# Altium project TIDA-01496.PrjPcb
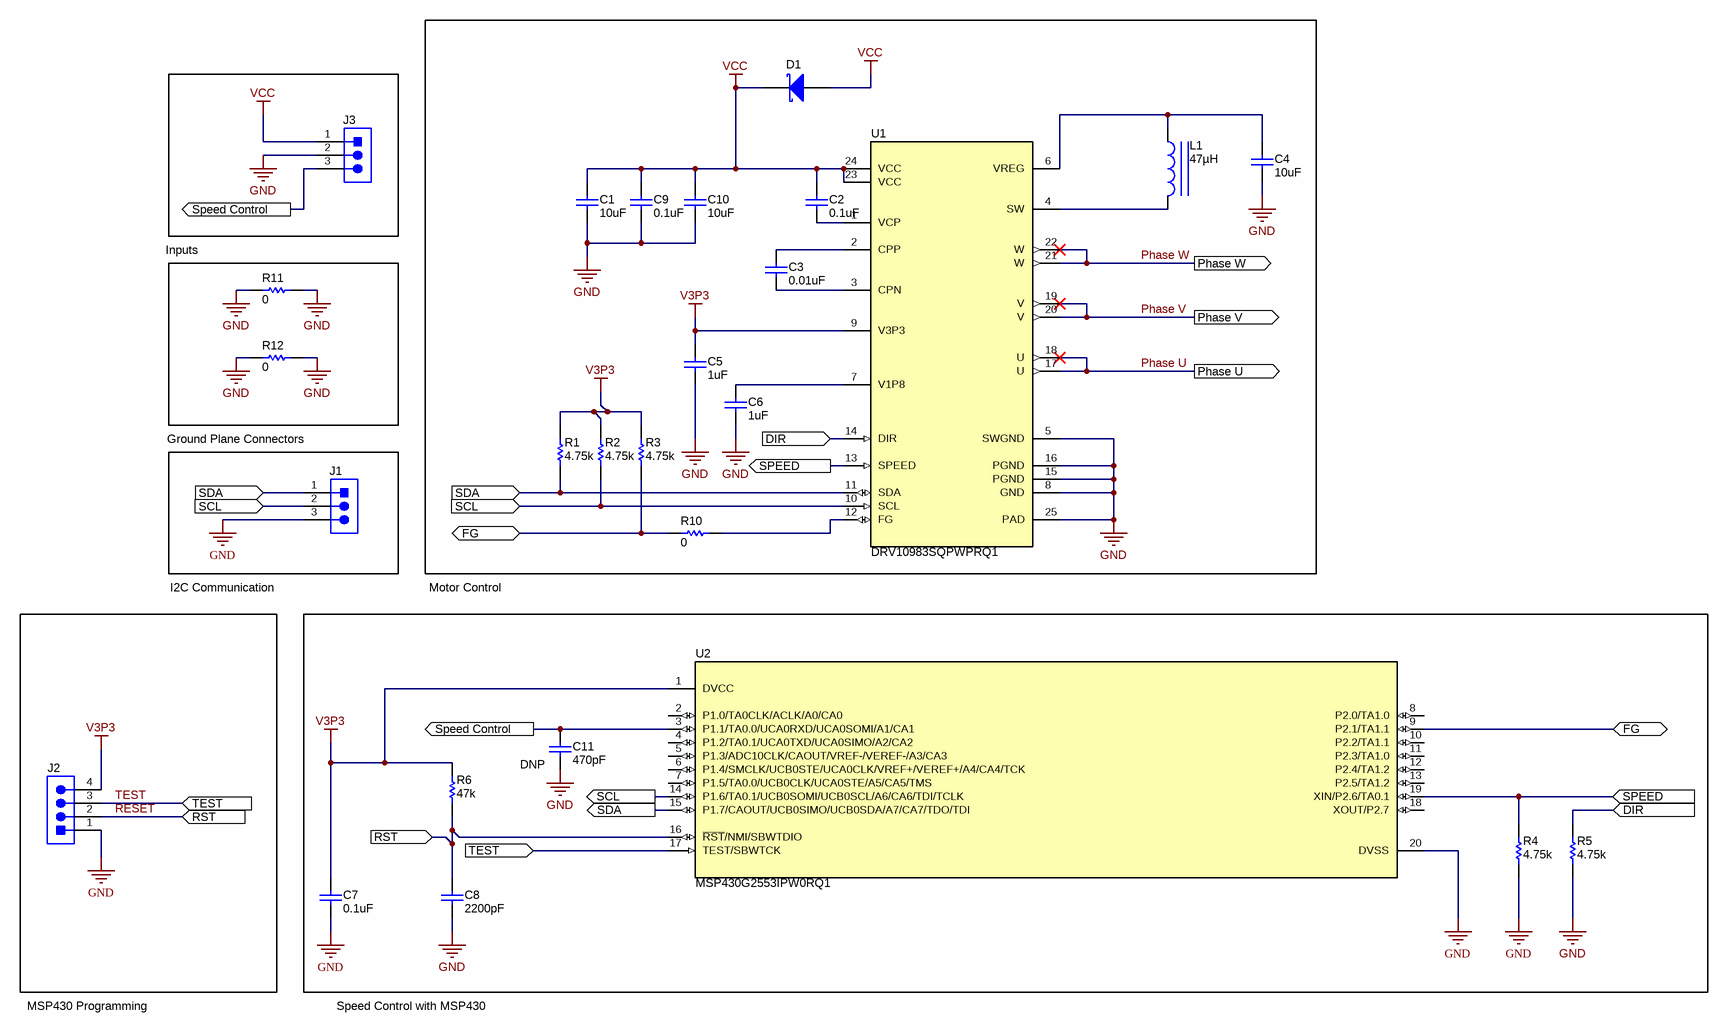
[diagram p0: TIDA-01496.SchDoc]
TID: TIDA-01496; TechSupport: http://www.ti.com/support; SCH_Rev: E2; PRJ_Title: Single-Layer, 12V, Programmable 3-Phase BLDC Motor Driver with Speed Regulation; PRJ_Number: TIDA-01496; PRJ_Engineer: Mostafa Subbar; PRJ_Customer: Public Release; PCB_Rev: E2; PCB_Layout: Mostafa Shubbar; CopyrightYear: 2018
2 sheets, 30 parts. Net scope: flat (ports and power ports of the same name join across sheets).
Board file: TIDA-01496_PCB.PcbDoc
Sheets:
  TIDA-01496.SchDoc
  TIDA-01496_Hardware.SchDoc

## Sheet TIDA-01496.SchDoc
size 431 x 279 mm; Date: Not shown in title block; ApprovedBy: Not shown in title block; CheckedBy: Not shown in title block; Author: Not shown in title block; CompanyName: Not shown in title block; Engineer: Not shown in title block; Organization: Not shown in title block; Address1: Not shown in title block; Address2: Not shown in title block; Address3: Not shown in title block; Address4: Not shown in title block; DocumentNumber: 1; Revision: Use project parameter SCH_Rev; SheetNumber: 1; SheetTotal: 2; PageSetup: Record=PageOptions¦CenterHorizontal=True¦CenterVertical=True¦PrintScale=1.00¦XCorrection=1.00¦YCorrection=1.00¦PrintKind=0¦BorderSize=5000000¦LeftOffset=0¦BottomOffset=0¦Orientation=2¦PaperLength=1000¦PaperWidth=1000¦Scale=100¦PaperSource=15¦PrintQuality=600¦MediaType=1¦DitherType=10¦PrintScaleMode=1¦PaperKind=Letter

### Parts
C1  ValueDisplayed: 10uF  [1206]  (hidden comment: Capacitor)
C2  ValueDisplayed: 0.1uF  [1206_180]  (hidden comment: Capacitor)
C3  ValueDisplayed: 0.01uF  [0603]  (hidden comment: Capacitor)
C4  ValueDisplayed: 10uF  [0603]  (hidden comment: Capacitor)
C5  ValueDisplayed: 1uF  [0603]  (hidden comment: Capacitor)
C6  ValueDisplayed: 1uF  [0603]  (hidden comment: Capacitor)
C7  ValueDisplayed: 0.1uF  [1206]  (hidden comment: Capacitor)
C8  ValueDisplayed: 2200pF  [0805_HV]  (hidden comment: Capacitor)
C9  ValueDisplayed: 0.1uF  [0603]  (hidden comment: Capacitor)
C10  ValueDisplayed: 10uF  [0603]  (hidden comment: Capacitor)
C11  ValueDisplayed: 470pF  [0603]  (hidden comment: Capacitor)
D1  DIODE_SCHOTTKY  [SOD-123FL]  (value not drawn)
J1  TSW-103-07-G-S  [TSW-103-07-G-S]  (value not drawn)
J2  TSW-104-07-G-S  [TSW-104-07-G-S]  (value not drawn)
J3  TSW-103-07-G-S  [TSW-103-07-G-S]  (value not drawn)
L1  ValueDisplayed: 47µH  [WE-PDA_7345]  (hidden comment: 784777470)
R1  ValueDisplayed: 4.75k  [0603]  (hidden comment: Resistor)
R2  ValueDisplayed: 4.75k  [0603]  (hidden comment: Resistor)
R3  ValueDisplayed: 4.75k  [0603]  (hidden comment: Resistor)
R4  ValueDisplayed: 4.75k  [0603]  (hidden comment: Resistor)
R5  ValueDisplayed: 4.75k  [0603]  (hidden comment: Resistor)
R6  ValueDisplayed: 47k  [0603]  (hidden comment: Resistor)
R10  ValueDisplayed: 0  [2010]  (hidden comment: Resistor)
R11  ValueDisplayed: 0  [2010]  (hidden comment: Resistor)
R12  ValueDisplayed: 0  [2010]  (hidden comment: Resistor)
U1  DRV10983SQPWPRQ1  [PWP0024B_N]
U2  MSP430G2553IPW0RQ1  [PW0020A_N]

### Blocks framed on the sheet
Inputs: R11 R12
Ground Plane Connectors: J1

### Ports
DIR (in), FG (bidir), Phase U (out), Phase V (out), Phase W (out), RST (in), SCL, SCL (in), SDA, SDA (in), SPEED, SPEED (in), Speed Control, TEST (in)

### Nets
GND: C1.2 C4.2 C5.1 C6.1 C7.2 C8.2 C9.2 C10.2 C11.2 J1.3 J2.1 J3.2 R4.1 R5.1 R11.1 R11.2 R12.1 R12.2 U1.5(SWGND) U1.8(GND) U1.15(PGND) U1.16(PGND) U1.25(PAD) U2.20(DVSS)
V3P3: C5.2 C7.1 J2.4 R1.2 R2.2 R3.2 R6.2 U1.9(V3P3) U2.1(DVCC)
VCC: C1.1 C2.1 C9.1 C10.1 D1.1(K) D1.2(A) J3.1 U1.23(VCC) U1.24(VCC)
DIR: R5.2 U1.14(DIR) ; port DIR
FG: R3.1 R10.2 U2.9(P2.1/TA1.1) ; port FG
Phase U: U1.17(U) U1.18(U) ; port Phase U
Phase V: U1.19(V) U1.20(V) ; port Phase V
Phase W: U1.21(W) U1.22(W) ; port Phase W
RESET: C8.1 J2.2 R6.1 U2.16(~{RST}/NMI/SBWTDIO) ; port RST
SCL: J1.2 R2.1 U1.10(SCL) U2.14(P1.6/TA0.1/UCB0SOMI/UCB0SCL/A6/CA6/TDI/TCLK) ; port SCL
SDA: J1.1 R1.1 U1.11(SDA) U2.15(P1.7/CAOUT/UCB0SIMO/UCB0SDA/A7/CA7/TDO/TDI) ; port SDA
SPEED: R4.2 U1.13(SPEED) U2.19(XIN/P2.6/TA0.1) ; port SPEED
Speed Control: C11.1 J3.3 U2.3(P1.1/TA0.0/UCA0RXD/UCA0SOMI/A1/CA1) ; port Speed Control
TEST: J2.3 U2.17(TEST/SBWTCK) ; port TEST
NetC2_2: C2.2 U1.1(VCP)
NetC3_1: C3.1 U1.2(CPP)
NetC3_2: C3.2 U1.3(CPN)
NetC4_1: C4.1 L1.1 U1.6(VREG)
NetC6_2: C6.2 U1.7(V1P8)
NetL1_2: L1.2 U1.4(SW)
NetR10_1: R10.1 U1.12(FG)

Not connected (* = marked no-connect by the designer): U2 2(P1.0/TA0CLK/ACLK/A0/CA0) 4(P1.2/TA0.1/UCA0TXD/UCA0SIMO/A2/CA2) 5(P1.3/ADC10CLK/CAOUT/VREF-/VEREF-/A3/CA3) 6(P1.4/SMCLK/UCB0STE/UCA0CLK/VREF+/VEREF+/A4/CA4/TCK) 7(P1.5/TA0.0/UCB0CLK/UCA0STE/A5/CA5/TMS) 8(P2.0/TA1.0) 10(P2.2/TA1.1) 11(P2.3/TA1.0) 12(P2.4/TA1.2) 13(P2.5/TA1.2) 18(XOUT/P2.7)

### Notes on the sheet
- I2C Communication
- Motor Control
- (near C11) DNP
- MSP430 Programming
- Speed Control with MSP430

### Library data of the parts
C1 = CMP-0008785-2: CAP, CERM, 10 uF, 50 V, +/- 20%, X5R, AEC-Q200 Grade 3, 1206; PartNumber: CGA5L3X5R1H106M160AB; Manufacturer: TDK; Polarized: N; Value: 10uF; U/M: EA; Cap_F: 10µF; Value1: Unknown; VDC_V: 50V; TaMin_C: -55°C; TaMax_C: 85°C; SizeArea_mm2: 5.12; SizeAreaWB_mm2: 10.92; SizeX_mm: 3.2; SizeY_mm: 1.6; SizeZ_mm: 1.35; AEC Category: Q200; AEC Qualified: Y; AEC Grade: 3
C2 = CMP-0064950-2: CAP, CERM, 0.1 uF, 25 V,+/- 5%, C0G/NP0, 1206; PartNumber: GRM31C5C1E104JA01L; Manufacturer: MuRata; Polarized: N; Value: 0.1uF; U/M: EA; Cap_F: 100nF; Value1: Unknown; VDC_V: 25V; TaMin_C: -55°C; TaMax_C: 125°C; Cap_Case: 1206; SizeArea_mm2: 5.12; SizeAreaWB_mm2: 10.92; SizeX_mm: 3.2; SizeY_mm: 1.6; SizeZ_mm: 1.8; AEC Category: Q200
C3 = CMP-0006854-4: CAP, CERM, 0.01 uF, 50 V, +/- 10%, X7R, 0603; PartNumber: C0603C103K5RACTU; Manufacturer: Kemet; Polarized: N; Value: 0.01uF; U/M: EA; Cap_F: 10nF; Value1: Unknown; VDC_V: 50V; TaMin_C: -55°C; TaMax_C: 125°C; SizeArea_mm2: 1.28; SizeAreaWB_mm2: 4.68; SizeX_mm: 1.6; SizeY_mm: 0.8; SizeZ_mm: 1; AEC Category: Q200
C4 = CMP-0007023-4: CAP, CERM, 10 uF, 10 V, +/- 10%, X6S, 0603; PartNumber: C1608X6S1A106M080AC; Manufacturer: TDK; Polarized: N; Value: 10uF; U/M: EA; Cap_F: 10µF; ESR_ohm: 4.639m; Value1: 0.004639 ohm; VDC_V: 10V; IRMS_A: 2.41407A; TaMin_C: -55°C; TaMax_C: 105°C; SizeArea_mm2: 1.28; SizeAreaWB_mm2: 4.68; SizeX_mm: 1.6; SizeY_mm: 0.8; SizeZ_mm: 1; AEC Category: Q200
C5 C6 = CMP-0007302-5: CAP, CERM, 1 uF, 6.3 V, +/- 10%, X5R, 0603; PartNumber: GRM188R60J105KA01D; Manufacturer: MuRata; Polarized: N; Value: 1uF; U/M: EA; Cap_F: 1µF; Value1: Unknown; VDC_V: 6.3V; TaMin_C: -55°C; TaMax_C: 85°C; SizeArea_mm2: 1.28; SizeAreaWB_mm2: 4.68; SizeX_mm: 1.6; SizeY_mm: 0.8; SizeZ_mm: 1; AEC Category: Q200
C7 = CMP-0008586-2: CAP, CERM, 0.1 uF, 50 V, +/- 10%, X7R, 1206; PartNumber: C1206C104K5RACTU; Manufacturer: Kemet; Polarized: N; Value: 0.1uF; U/M: EA; Cap_F: 100nF; ESR_ohm: 0.059; Value1: 0.059 ohm; VDC_V: 50V; IRMS_A: 1.2A; TaMin_C: -55°C; TaMax_C: 125°C; SizeArea_mm2: 5.12; SizeAreaWB_mm2: 10.92; SizeX_mm: 3.2; SizeY_mm: 1.6; SizeZ_mm: 1.35; AEC Category: Q200
C8 = CMP-0007601-2: CAP, CERM, 2200 pF, 50 V, +/- 5%, C0G/NP0, 0805; PartNumber: 08055A222JAT2A; Manufacturer: AVX; Polarized: N; Value: 2200pF; U/M: EA; Cap_F: 2.2nF; ESR_ohm: 0.08; Value1: 0.08 ohm; VDC_V: 50V; TaMin_C: -55°C; TaMax_C: 125°C; Cap_Case: 0805; SizeArea_mm2: 2.5; SizeAreaWB_mm2: 6.75; SizeX_mm: 2; SizeY_mm: 1.25; SizeZ_mm: 1.45; AEC Category: Q200
C9 = CMP-0006802-4: CAP, CERM, 0.1 uF, 50 V, +/- 10%, X7R, 0603; PartNumber: 06035C104KAT2A; Manufacturer: AVX; Polarized: N; Value: 0.1uF; U/M: EA; Cap_F: 100nF; Value1: Unknown; VDC_V: 50V; TaMin_C: -55°C; TaMax_C: 125°C; SizeArea_mm2: 1.28; SizeAreaWB_mm2: 4.68; SizeX_mm: 1.6; SizeY_mm: 0.8; SizeZ_mm: 1; AEC Category: Q200
C10 = CMP-0007007-5: CAP, CERM, 10 uF, 25 V, +/- 20%, X5R, 0603; PartNumber: C1608X5R1E106M080AC; Manufacturer: TDK; Polarized: N; Value: 10uF; U/M: EA; Cap_F: 10µF; ESR_ohm: 4.639m; Value1: 0.004639 ohm; VDC_V: 25V; IRMS_A: 2.41407A; TaMin_C: -55°C; TaMax_C: 85°C; SizeArea_mm2: 1.28; SizeAreaWB_mm2: 4.68; SizeX_mm: 1.6; SizeY_mm: 0.8; SizeZ_mm: 1; AEC Category: Q200
C11 = CMP-0006790-4: CAP, CERM, 470 pF, 50 V, +/- 5%, C0G/NP0, 0603; PartNumber: 06035A471JAT2A; Manufacturer: AVX; Polarized: N; Value: 470pF; U/M: EA; ESR_ohm: 0.063; Value1: 0.063 ohm; VDC_V: 50V; TaMin_C: -55°C; TaMax_C: 125°C; SizeArea_mm2: 1.28; SizeAreaWB_mm2: 4.68; SizeX_mm: 1.6; SizeY_mm: 0.8; SizeZ_mm: 1; AEC Category: Q200
D1 = CMP-0028770-1: Diode, Schottky, 30 V, 2 A, AEC-Q101, SOD-123FL; PartNumber: MBR230LSFT1G; Manufacturer: ON Semiconductor; U/M: EA; Vf_V: 4.3dV; Value: 30V; Value1: 2A; Value2: 0.43V; TJmax_C: 125°C; RJC_CperW: 26; SizeAreaWB_mm2: 12.19; SizeArea_mm2: 5.94; SizeX_mm: 3.6; SizeY_mm: 1.65; SizeZ_mm: 0.98; AEC Category: Q101; AEC Qualified: Y; Green_Lifecycle: Not Set; Green_REACh: Incomplete
J1 J3 = CMP-0075407-2: Header, 100mil, 3x1, Gold, TH; Manufacturer: Samtec; Pitch_mm: 2.54; Cert_VDE: N; Gender: Male; Cert_CSA: Y; Voltage_V: 550V; Green_REACh: Passed; Current_A: 6.3A; Green_Lifecycle: Active; Row_Count: 1
J2 = CMP-0075409-2: Header, 100mil, 4x1, Gold, TH; Manufacturer: Samtec; Pitch_mm: 2.54; Cert_VDE: N; Gender: Male; Cert_CSA: Y; Voltage_V: 550V; Green_REACh: Passed; Current_A: 6.3A; Green_Lifecycle: Active; Row_Count: 1
L1 = CMP-0078174-2: Inductor, Shielded, Ferrite, 47 µH, 1.15 A, .3 ohm, AEC-Q200 Grade 1, SMD; Manufacturer: Wurth Elektronik; SizeAreaWB_mm2: 86.49; Irms: 1.15A @ 40C rise; SizeArea_mm2: 53.29; AEC Qualified: Y; AEC Category: Q200; Value: 47uH; SizeZ_mm: 4.3; Imax_A: 1.15A; AEC Grade: 1; SizeY_mm: 7.3; Isat: 1.25A @ 10% inductance drop; Value1: .3 ohm; DCR_ohm: 3d
R1-R5 = CMP-0022456-4: RES, 4.75 k, 1%, 0.1 W, AEC-Q200 Grade 0, 0603; PartNumber: CRCW06034K75FKEA; Manufacturer: Vishay-Dale; Value: 4.75k; Value_Code: 4k75; Power_W: 100mW; Value2: 0.1W; VDC_V: 75V; TempCo: 100 ppm/C; SizeArea_mm2: 1.28; SizeX_mm: 1.6; SizeY_mm: 0.8; SizeZ_mm: 1; EIA_Code: E96; AEC Category: Q200; AEC Qualified: Y; AEC Grade: 0
R6 = CMP-0025814-4: RES, 47 k, 5%, 0.1 W, AEC-Q200 Grade 0, 0603; PartNumber: CRCW060347K0JNEA; Manufacturer: Vishay-Dale; Value: 47k; Value_Code: 47k0; Power_W: 100mW; Value2: 0.1W; VDC_V: 75V; TempCo: 200 ppm/C; SizeArea_mm2: 1.28; SizeX_mm: 1.6; SizeY_mm: 0.8; SizeZ_mm: 1; EIA_Code: E24; AEC Category: Q200; AEC Qualified: Y; AEC Grade: 0
R10-R12 = CMP-0016044-3: RES, 0, 5%, 0.75 W, AEC-Q200 Grade 0, 2010; PartNumber: CRCW20100000Z0EF; Manufacturer: Vishay-Dale; Value: 0; Value_Code: 0000; Power_W: 750mW; Value2: 0.75W; TempCo: ppm/C; SizeArea_mm2: 12.5; SizeX_mm: 5; SizeY_mm: 2.5; SizeZ_mm: 1.66; EIA_Code: E24; AEC Category: Q200; AEC Qualified: Y
U1 = CMP-0065210-4: Automotive, Three-Phase, Sensorless BLDC Motor Driver, PWP0024B (TSSOP-24); Manufacturer: Texas Instruments; SizeX_mm: 6.4; SizeY_mm: 7.8; CompType: IC; SizeZ_mm: 1.2; SizeArea_mm2: 49.92; SizeAreaWB_mm2: 82.32; U/M: EA
U2 = CMP-0081287-1: MSP430(TM) Ultra-Low-Power Microcontrollers for Automotive Applications, PW0020A (TSSOP-20); Alternate Manufacturer: Texas Instruments; SizeAreaWB_mm2: 73.96; SizeZ_mm: 1.2; SizeX_mm: 6.6; SizeArea_mm2: 43.56; CompType: IC; AEC Qualified: Y; AEC Category: Q200

## Sheet TIDA-01496_Hardware.SchDoc
size 431 x 279 mm; Date: Not shown in title block; ApprovedBy: Not shown in title block; CheckedBy: Not shown in title block; Author: Not shown in title block; CompanyName: Not shown in title block; Engineer: Not shown in title block; Organization: Not shown in title block; Address1: Not shown in title block; Address2: Not shown in title block; Address3: Not shown in title block; Address4: Not shown in title block; DocumentNumber: 1; Revision: Use project parameter SCH_Rev; SheetNumber: 2; SheetTotal: 2; PageSetup: Record=PageOptions¦CenterHorizontal=True¦CenterVertical=True¦PrintScale=1.00¦XCorrection=1.00¦YCorrection=1.00¦PrintKind=0¦BorderSize=5000000¦LeftOffset=0¦BottomOffset=0¦Orientation=2¦PaperLength=1000¦PaperWidth=1000¦Scale=100¦PaperSource=15¦PrintQuality=600¦MediaType=1¦DitherType=10¦PaperKind=Letter¦PrintScaleMode=1
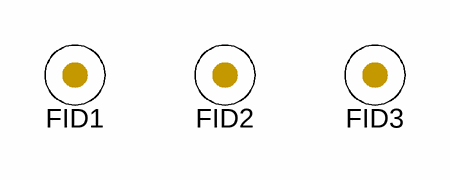
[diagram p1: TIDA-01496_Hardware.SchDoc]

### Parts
FID1  Fiducial  [Fiducial6.4-20]  (value not drawn)
FID2  Fiducial  [Fiducial6.4-20]  (value not drawn)
FID3  Fiducial  [Fiducial6.4-20]  (value not drawn)

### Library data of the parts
FID1-FID3 = CMP-0077181-1: Fiducial mark.  There is nothing to buy or mount.

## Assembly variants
001: not fitted FID1 FID2 FID3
